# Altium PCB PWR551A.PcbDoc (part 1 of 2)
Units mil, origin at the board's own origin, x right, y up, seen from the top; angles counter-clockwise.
Board outline 7100 x 3800 mil, 2 copper layers (Top Layer, Bottom Layer), stack 62 mil thick; 141 components, 57 nets, 323 pads, 168 vias.
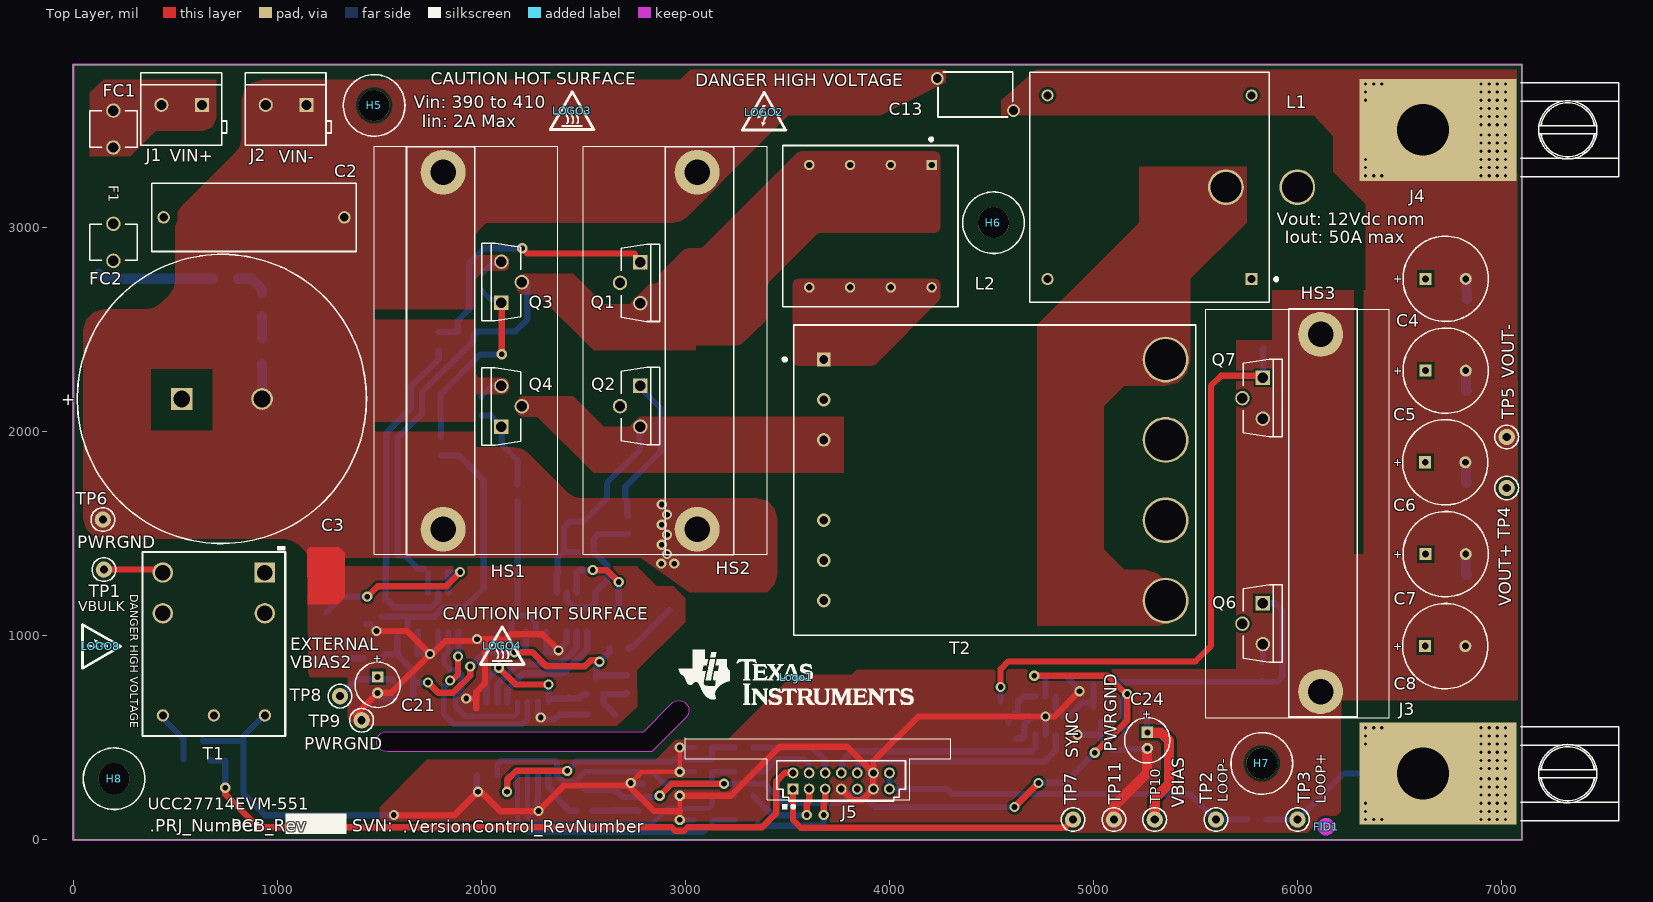
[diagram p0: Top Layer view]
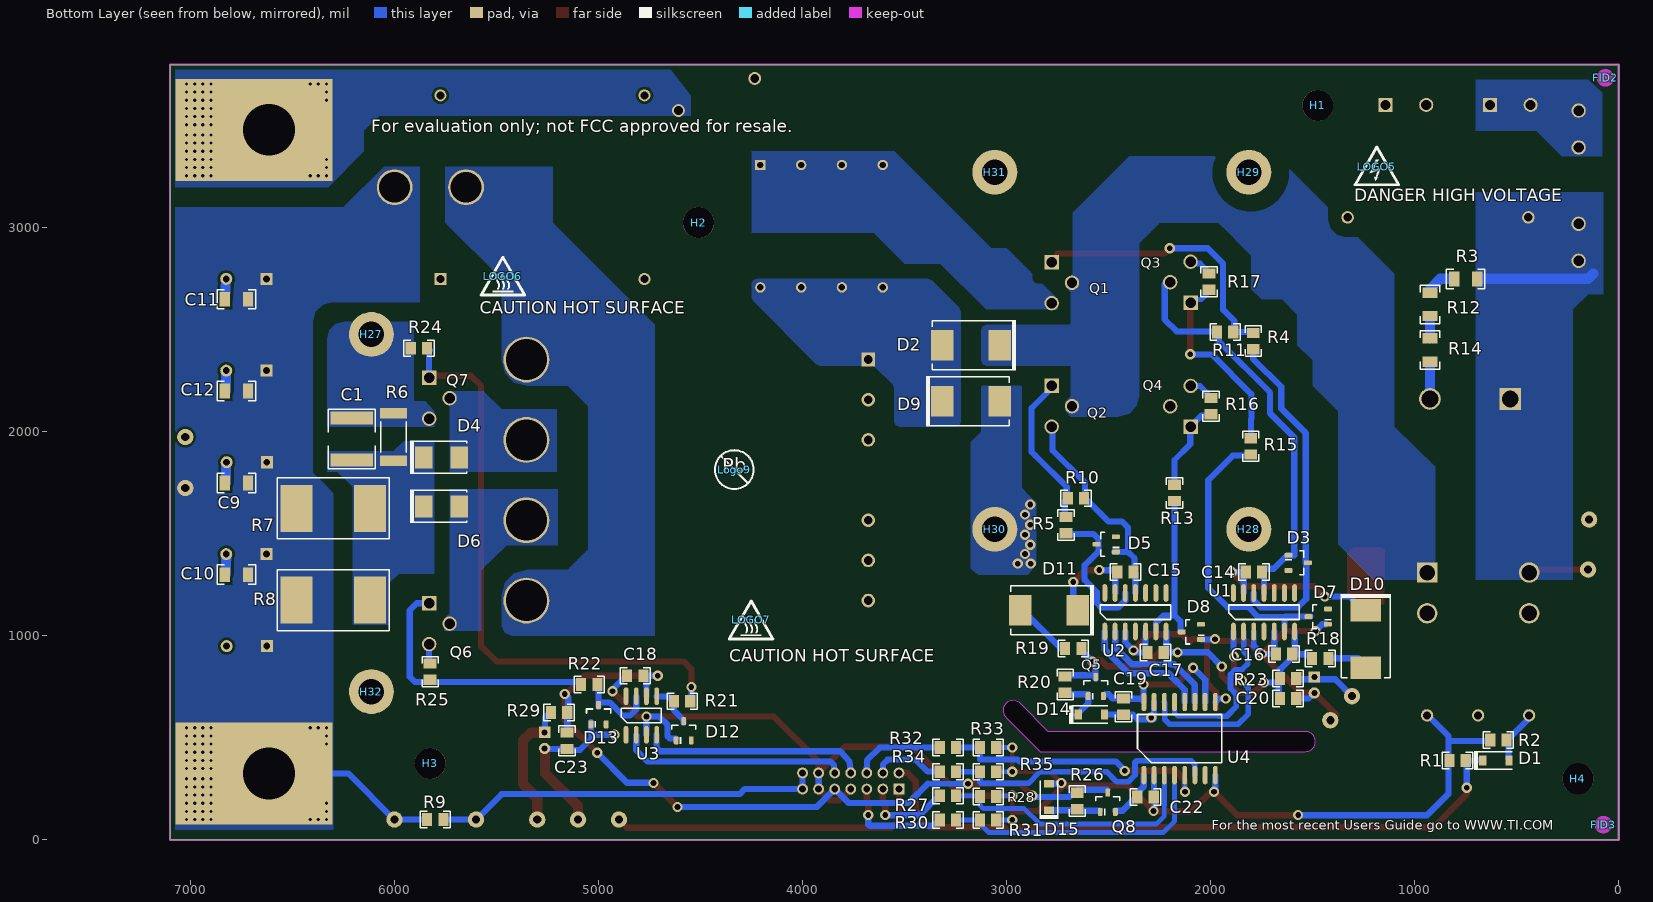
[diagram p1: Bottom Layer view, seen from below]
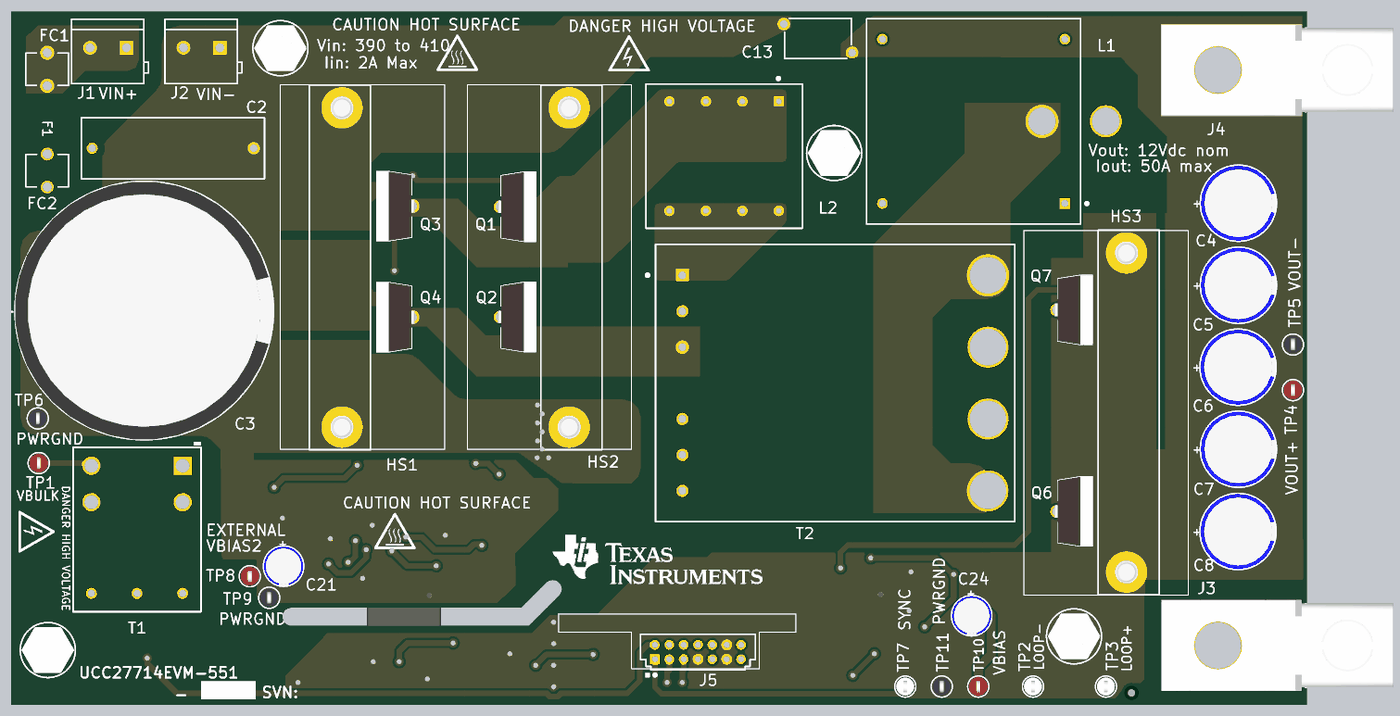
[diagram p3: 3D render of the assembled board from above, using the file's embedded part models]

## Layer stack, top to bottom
Top Layer: signal copper 1.4
Dielectric: core 59.2, FR-4, Dk 4.8
Bottom Layer: signal copper 1.4

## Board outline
0,0 0,3800 7100,3800 7100,0
cut-out: 1535.43,433.07 cw(c1535.43,482.28) 1535.43,531.5 2795.28,531.5 2933.07,669.29 cw(c2967.87,634.49) 3002.67,599.69 2836.04,433.07

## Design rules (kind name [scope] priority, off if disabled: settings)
AcuteAngle [All] p1: minimum=4.50000000000000E+0001 checktracksonly=TRUE
AssemblyTestPointUsage [All] p1: valid=2
Clearance Clearance-PRI-SEC [InNetClass('SEC') vs InNetClass('HV') OR InNetClass('SW') OR InNetClass('LV')] p1: gap=314.96
Clearance ClearanceHV [InNetClass('HV') vs InNetClass('All Nets')] p2: gap=39.37
Clearance ClearanceSW [InNetClass('SW') vs InNetClass('HV') OR InNetClass('LV')] p3: gap=39.37
Clearance Clearance_Poly [InPolygon] p4: gap=12
Clearance Clearance_BoardEdge_MountingHoles [OnCopper and InComponentClass('Mounting Holes') vs IsKeepOut] p5: gap=12
Clearance Clearance_BoardEdge_Poly [OnCopper and InPoly vs IsKeepOut] p6: gap=19.68
Clearance Clearance_BoardEdge [OnCopper and Not InComponentClass('Logo') and not InComponentClass('FiducialMark') and not InRegion(1000,500,4000,800) and Not IsKeepout vs IsKeepout] p7: gap=19.68
Clearance Clearance_ALL [All] p8: gap=12
ComponentClearance ComponentClearance_Logo [InComponentClass(Logo)] p1: gap=3.94 collisioncheckmode=3 verticalgap=27.56 showdistances=FALSE
ComponentClearance ComponentClearance_ScrewToNut [(HasFootprint('NY PMS 440 0025 PH')) vs (HasFootprint('Keystone_1902C'))] p2: gap=0 collisioncheckmode=3 verticalgap=0 showdistances=FALSE
ComponentClearance ComponentClearance_MountingHoles [InComponentClass('Mounting Holes')] p3: gap=19.68 collisioncheckmode=3 verticalgap=27.56 showdistances=FALSE
ComponentClearance ComponentClearance_SmallPassives [HasFootprint('0201*') or HasFootprint('0402*') or HasFootprint('0508') or HasFootprint('0603*') or HasFootprint('0612') or HasFootprint('0805*') or HasFootprint('0815*') or HasFootprint('0830*') or HasFootprint('1206*') or HasFootprint('1210*') or HasFootprint('1808*') or HasFootprint('1812*') or HasFootprint('1825*') or HasFootprint('2010*') or HasFootprint('2220*') or HasFootprint('2225*') or HasFootprint('2512*') or HasFootprint('2728*') or HasFootprint('3518*') vs HasFootprint('0201*') or HasFootprint('0402*') or HasFootprint('0508') or HasFootprint('0603*') or HasFootprint('0612') or HasFootprint('0805*') or HasFootprint('0815*') or HasFootprint('0830*') or HasFootprint('1206*') or HasFootprint('1210*') or HasFootprint('1808*') or HasFootprint('1812*') or HasFootprint('1825*') or HasFootprint('2010*') or HasFootprint('2220*') or HasFootprint('2225*') or HasFootprint('2512*') or HasFootprint('2728*') or HasFootprint('3518*')] p4: gap=7.87 collisioncheckmode=3 verticalgap=10 showdistances=FALSE
ComponentClearance ComponentClearance_THtoSMT [IsThruComponent vs IsSMTComponent] p5 off: gap=7.87 collisioncheckmode=3 verticalgap=27.56 showdistances=FALSE
ComponentClearance ComponentClearance_THtoTH [IsThruComponent vs IsThruComponent] p6 off: gap=7.87 collisioncheckmode=3 verticalgap=27.56 showdistances=FALSE
ComponentClearance [All] p7: gap=0 collisioncheckmode=3 verticalgap=0 showdistances=FALSE
DiffPairsRouting [All] p1: maxlimit=100 minlimit=10 mostfreqgap=10 maxuncoupledlength=1000
FabricationTestPointUsage TestPointUsage [All] p1: valid=2 allowmultiple=FALSE
FabricationTestpoint Testpoint [All] p1: side=3 testpointundercomponent=TRUE minsize=40 maxsize=100 preferedsize=60 minholesize=0 maxholesize=40 preferedholesize=32 testpointgrid=1 allowsidetop=TRUE allowsidebottom=TRUE usegrid=TRUE gridtolerance=0.01
FanoutControl Fanout_LCC [IsLCC] p1: bgadir=Out bgaviamode=Centered fanoutstyle=Auto fanoutdirection=Alternating viagrid=1 // Fanout_LCC (Default Rule)
FanoutControl Fanout_BGA [IsBGA] p2: bgadir=Out bgaviamode=Centered fanoutstyle=Auto fanoutdirection=Alternating viagrid=1 // Fanout_BGA (Default Rule)
FanoutControl Fanout_Default [All] p4: bgadir=Out bgaviamode=Centered fanoutstyle=Auto fanoutdirection=Alternating viagrid=1 // Fanout_Default (Default Rule)
FanoutControl Fanout_Small [(CompPinCount < 5)] p5: bgadir=Out bgaviamode=Centered fanoutstyle=Auto fanoutdirection=OutThenIn viagrid=1 // Fanout_Small (Default Rule)
Height "Height Bottom" [(OnLayer('Bottom Layer'))] p1: minheight=0 maxheight=1000 prefheight=500
Height Height_top [(OnLayer('Top Layer'))] p2: minheight=0 maxheight=1750 prefheight=1750
HoleSize [All] p1: absolutevalues=TRUE maxlimit=275.59 minlimit=8 maxpercent=80.000 minpercent=20.000
MinimumAnnularRing [All] p1: minimumring=8
MinimumSolderMaskSliver MinimumSolderMaskSliver_Logo [InComponentClass('Logo') vs InComponentClass('Logo')] p1: minsoldermaskwidth=0.7
MinimumSolderMaskSliver [All] p2: minsoldermaskwidth=4
PlaneConnect [All] p1: planeconnectstyle=Relief reliefexpansion=10 reliefentries=4 reliefconductorwidth=10 reliefairgap=10
PolygonConnect PolygonConnect_23 [All vs IsNamedPolygon('Top Layer, Top-PWRGND 4')] p1: connectstyle=Direct reliefconductorwidth=10 reliefentries=4 polygonreliefangle="90 Angle" airgapwidth=10
PolygonConnect PolygonConnect_22 [All vs IsNamedPolygon('Top Layer, Top-PWRGND 4')] p2: connectstyle=Direct reliefconductorwidth=10 reliefentries=4 polygonreliefangle="90 Angle" airgapwidth=10
PolygonConnect PolygonConnect_21 [All vs IsNamedPolygon('Top Layer, Top-PWRGND 2')] p3: connectstyle=Direct reliefconductorwidth=10 reliefentries=4 polygonreliefangle="90 Angle" airgapwidth=10
PolygonConnect PolygonConnect_20 [All vs IsNamedPolygon('Top Layer, Top-PWRGND 3')] p4: connectstyle=Direct reliefconductorwidth=10 reliefentries=4 polygonreliefangle="90 Angle" airgapwidth=10
PolygonConnect PolygonConnect_19 [All vs IsNamedPolygon('Top Layer, Top-PWRGND 4')] p5: connectstyle=Direct reliefconductorwidth=10 reliefentries=4 polygonreliefangle="90 Angle" airgapwidth=10
PolygonConnect PolygonConnect_18 [All vs IsNamedPolygon('Top Layer, Top-GND')] p6: connectstyle=Direct reliefconductorwidth=10 reliefentries=4 polygonreliefangle="90 Angle" airgapwidth=10
PolygonConnect PolygonConnect_17 [All vs IsNamedPolygon('Top Layer, Top-GND 1')] p7: connectstyle=Direct reliefconductorwidth=10 reliefentries=4 polygonreliefangle="90 Angle" airgapwidth=10
PolygonConnect PolygonConnect_16 [All vs IsNamedPolygon('Top Layer, Top-GND 2')] p8: connectstyle=Direct reliefconductorwidth=10 reliefentries=4 polygonreliefangle="90 Angle" airgapwidth=10
PolygonConnect PolygonConnect_15 [All vs IsNamedPolygon('Top Layer, Top-NET00002')] p9: connectstyle=Direct reliefconductorwidth=10 reliefentries=4 polygonreliefangle="90 Angle" airgapwidth=10
PolygonConnect PolygonConnect_14 [All vs IsNamedPolygon('Top Layer, Top-NET00003')] p10: connectstyle=Direct reliefconductorwidth=10 reliefentries=4 polygonreliefangle="90 Angle" airgapwidth=10
PolygonConnect PolygonConnect_13 [All vs IsNamedPolygon('Top Layer, Top-NET00003')] p11: connectstyle=Direct reliefconductorwidth=10 reliefentries=4 polygonreliefangle="90 Angle" airgapwidth=10
PolygonConnect PolygonConnect_12 [All vs IsNamedPolygon('Top Layer, Top-NET00007')] p12: connectstyle=Direct reliefconductorwidth=10 reliefentries=4 polygonreliefangle="90 Angle" airgapwidth=10
PolygonConnect PolygonConnect_11 [All vs IsNamedPolygon('Top Layer, Top-NET00016')] p13: connectstyle=Direct reliefconductorwidth=10 reliefentries=4 polygonreliefangle="90 Angle" airgapwidth=10
PolygonConnect PolygonConnect_10 [All vs IsNamedPolygon('Top Layer, Top-NET00025')] p14: connectstyle=Direct reliefconductorwidth=10 reliefentries=4 polygonreliefangle="90 Angle" airgapwidth=10
PolygonConnect PolygonConnect_9 [All vs IsNamedPolygon('Top Layer, Top-NET00025 1')] p15: connectstyle=Direct reliefconductorwidth=10 reliefentries=4 polygonreliefangle="90 Angle" airgapwidth=10
PolygonConnect PolygonConnect_8 [All vs IsNamedPolygon('Top Layer, Top-No Net')] p16: connectstyle=Direct reliefconductorwidth=10 reliefentries=4 polygonreliefangle="90 Angle" airgapwidth=10
PolygonConnect PolygonConnect_7 [All vs IsNamedPolygon('Top Layer, Top-PWRGND')] p17: connectstyle=Direct reliefconductorwidth=10 reliefentries=4 polygonreliefangle="90 Angle" airgapwidth=10
PolygonConnect PolygonConnect_6 [All vs IsNamedPolygon('Top Layer, Top-PWRGND 1')] p18: connectstyle=Direct reliefconductorwidth=10 reliefentries=4 polygonreliefangle="90 Angle" airgapwidth=10
PolygonConnect PolygonConnect_5 [All vs IsNamedPolygon('Top Layer, Top-PWRGND 2')] p19: connectstyle=Direct reliefconductorwidth=10 reliefentries=4 polygonreliefangle="90 Angle" airgapwidth=10
PolygonConnect PolygonConnect_4 [All vs IsNamedPolygon('Top Layer, Top-PWRGND 3')] p20: connectstyle=Direct reliefconductorwidth=10 reliefentries=4 polygonreliefangle="90 Angle" airgapwidth=10
PolygonConnect PolygonConnect_3 [All vs IsNamedPolygon('Top Layer, Top-PWRGND 4')] p21: connectstyle=Direct reliefconductorwidth=10 reliefentries=4 polygonreliefangle="90 Angle" airgapwidth=10
PolygonConnect PolygonConnect_2 [All vs IsNamedPolygon('Top Layer, Top-PWRGND 3') Or  IsNamedPolygon('Top Layer, Top-PWRGND 4')] p22: connectstyle=Direct reliefconductorwidth=10 reliefentries=4 polygonreliefangle="90 Angle" airgapwidth=10
PolygonConnect PolygonConnect_1 [All vs IsNamedPolygon('Top Layer, Top-PWRGND 2') Or  IsNamedPolygon('Bottom Layer, Bottom-GND') Or  IsNamedPolygon('Bottom Layer, Bottom-NET00038') Or  IsNamedPolygon('Bottom Layer, Bottom-NET00006') Or  IsNamedPolygon('Bottom Layer, Bottom-NET00003') Or  IsNamedPolygon('Bottom Layer, Bottom-NET00004 2') Or  IsNamedPolygon('Bottom Layer, Bottom-NET00020') Or  IsNamedPolygon('Bottom Layer, Bottom-GND 2') Or  IsNamedPolygon('Bottom Layer, Bottom-NET00004') Or  IsNamedPolygon('Bottom Layer, Bottom-PWRGND') Or  IsNamedPolygon('Bottom Layer, Bottom-NET00002 1') Or  IsNamedPolygon('Bottom Layer, Bottom-NET00013') Or  IsNamedPolygon('Bottom Layer, Bottom-NET00012') Or  IsNamedPolygon('Bottom Layer, Bottom-NET00004 3') Or  IsNamedPolygon('Bottom Layer, Bottom-NET00004 1') Or  IsNamedPolygon('Bottom Layer, Bottom-NET00016') Or  IsNamedPolygon('Bottom Layer, Bottom-GND 1') Or  IsNamedPolygon('Bottom Layer, Bottom-NET00025') Or  IsNamedPolygon('Bottom Layer, Bottom-NET00002') Or  IsNamedPolygon('Top Layer, Top-No Net') Or  IsNamedPolygon('Top Layer, Top-NET00016') Or  IsNamedPolygon('Top Layer, Top-NET00025 1') Or  IsNamedPolygon('Top Layer, Top-GND 2') Or  IsNamedPolygon('Top Layer, Top-PWRGND 3') Or  IsNamedPolygon('Top Layer, Top-PWRGND 4') Or  IsNamedPolygon('Top Layer, Top-NET00002') Or  IsNamedPolygon('Top Layer, Top-NET00007') Or  IsNamedPolygon('Top Layer, Top-GND 1') Or  IsNamedPolygon('Top Layer, Top-PWRGND 1') Or  IsNamedPolygon('Top Layer, Top-GND') Or  IsNamedPolygon('Top Layer, Top-NET00025') Or  IsNamedPolygon('Top Layer, Top-NET00003') Or  IsNamedPolygon('Top Layer, Top-PWRGND')] p23: connectstyle=Direct reliefconductorwidth=10 reliefentries=4 polygonreliefangle="90 Angle" airgapwidth=10
PolygonConnect [All] p24: connectstyle=Relief reliefconductorwidth=10 reliefentries=4 polygonreliefangle="90 Angle" airgapwidth=10
RoutingVias [All] p1: holewidth=16 width=34 viastyle="Through Hole" minholewidth=8 minwidth=26 maxholewidth=40 maxwidth=65
SMDToCorner [All] p1: distance=30000
SilkToSilkClearance [All] p1 off: silktosilkclearance=4.5
SilkscreenOverComponentPads [All] p1: minsilkscreentomaskgap=5
SolderMaskExpansion [All] p1: expansion=3
Width [All] p1: maxlimit=100 minlimit=19.68 preferedwidth=31.5 checkconnectedcopper=TRUE
13 further rules are at their usual default settings.

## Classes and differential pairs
component class Screw: H27 H28 H29 H30 H31 H32
net class SW: NetC14_1 NetC15_1
net class HV: NetC2_2 NetD2_1 NetF1_1 NetF1_2 NetFC1_1 NetR3_1 NetR12_1
net class SEC: CS GND NetC1_2 NetC4_1 NetC22_2 NetC24_1 NetD1_2 NetD4_2 NetD6_2 NetD12_3 NetD13_3 NetD15_1 NetL1_13 NetQ6_1 NetQ7_1 NetR27_2 NetR30_2 NetR32_2 NetR34_2 NetU3_1 NetU3_8 NetU4_7 OUTA OUTB OUTC OUTD OUTE OUTF SYNC VBIAS VOUT
component class PWR551A_Sht01: C1 C2 C3 C4 C5 C6 C7 C8 C9 C10 C11 C12 C13 C14 C15 C16 C17 C18 C19 C20 C21 C22 C23 C24 D1 D2 D3 D4 D5 D6 D7 D8 D9 D10 D11 D12 D13 D14 D15 F1 FC1 FC2 HS1 HS2 HS3 J1 J2 J3 J4 J5 L1 L2 Q1 Q2 Q3 Q4 Q5 Q6 Q7 Q8 R1 R2 R3 R4 R5 R6 R7 R8 R9 R10 R11 R12 R13 R14 R15 R16 R17 R18 R19 R20 R21 R22 R23 R24 R25 R26 R27 R28 R29 R30 R31 R32 R33 R34 R35 T1 T2 TP1 TP2 TP3 TP4 TP5 TP6 TP7 TP8 TP9 TP10 TP11 U1 U2 U3 U4
component class PWR551A_Hardware: !PCB FID1 FID2 FID3 H1 H2 H3 H4 H5 H6 H7 H8 H27 H28 H29 H30 H31 H32 Logo1 LOGO2 LOGO3 LOGO4 LOGO5 LOGO6 LOGO7 LOGO8 Logo9 ZZ1 ZZ2 ZZ3 ZZ4
component class Logo: Logo1
component class FiducialMark: FID1 FID2 FID3
component class AssemblyNote: ZZ1 ZZ2 ZZ3 ZZ4

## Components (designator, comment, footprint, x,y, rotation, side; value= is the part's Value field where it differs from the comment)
C1 "C2220C224J1GACTU" 2220 6210,1965 r270 bottom
C2 "ECQ-U2A474ML" CAPRR2250W80L2550T850H1750 885.83,3051.18 r180 top
C3 "EET-HC2W331EA" TS-HC_3500x3500 728.35,2161.42 r0 top
C4 "EKY-160ELL152MJ30S" KY_1000x3000 6726,2750 r0 top
C5 "EKY-160ELL152MJ30S" KY_1000x3000 6726,2300 r0 top
C6 "EKY-160ELL152MJ30S" KY_1000x3000 6724,1851 r0 top
C7 "EKY-160ELL152MJ30S" KY_1000x3000 6726,1401 r0 top
C8 "EKY-160ELL152MJ30S" KY_1000x3000 6724,950 r0 top
C9 "C3216X7R1E105K085AA" 1206 6775,1750 r180 bottom
C10 "C3216X7R1E105K085AA" 1206 6775,1300 r180 bottom
C11 "C3216X7R1E105K085AA" 1206 6775,2650 r180 bottom
C12 "C3216X7R1E105K085AA" 1206 6775,2200 r180 bottom
C13 "440LD10-R" 440L_930x1250 4421.26,3653.54 r180 top
C14 "C2012X7R1H104K" 0805_HV 1787.8,1312.99 r0 bottom
C15 "C2012X7R1H104K" 0805_HV 2417.72,1312.99 r0 bottom
C16 "C2012X7R1E105K" 0805_HV 1640.16,910.87 r180 bottom
C17 "C2012X7R1E105K" 0805_HV 2270.08,919.29 r180 bottom
C18 "C2012X7R1E105K" 0805_HV 4820,805 r180 bottom
C19 "C2012X7R1E105K" 0805_HV 2427.56,653.54 r90 bottom
C20 "C2012X7R1E105K" 0805_HV 1620.47,692.91 r0 bottom
C21 "ECA-1VM220" M_500x1100 1492.13,759.84 r270 top
C22 "C2012X7R1E105K" 0805_HV 2319.29,210.63 r0 bottom
C23 "C2012X7R1E105K" 0805_HV 5153.94,486.22 r90 bottom
C24 "ECA-1VM220" M_500x1100 5263.78,488.19 r270 top
D1 "1N4148W-7-F" SOD-123 602.36,389.76 r180 bottom
D2 "MURS360T3G" SMC 3175,2425 r0 bottom
D3 "BAT54-7-F" SOT-23 1570.87,1358.27 r180 bottom
D4 "ES3BB-13-F" SMB 5770,1875 r180 bottom
D5 "BAT54-7-F" SOT-23 2511.81,1448.82 r0 bottom
D6 "ES3BB-13-F" SMB 5770,1635 r180 bottom
D7 "BAT54-7-F" SOT-23 1472.44,1094.49 r0 bottom
D8 "BAT54-7-F" SOT-23 2094.49,1019.68 r0 bottom
D9 "MURS360T3G" SMC 3175,2150 r180 bottom
D10 "MURS360T3G" SMC 1240.16,984.25 r270 bottom
D11 "MURS360T3G" SMC 2791.73,1125.98 r0 bottom
D12 "BAT54-7-F" SOT-23 4582.68,535.43 r90 bottom
D13 "BAT54-7-F" SOT-23 5000,614.17 r90 bottom
D14 "MMSZ5232B-7-F" SOD-123 2585.04,614.17 r180 bottom
D15 "MMSZ5232B-7-F" SOD-123 2791.73,210.63 r90 bottom
FC1 "01000056Z" Littelfuse_0100-0020_54_56 196.85,3484.25 r90 top
FC2 "01000056Z" Littelfuse_0100-0020_54_56 196.85,2929.13 r270 top
FID1 "Fiducial" Fiducial10-20 6140,65 r0 top
FID2 "Fiducial" Fiducial10-20 65,3735 r180 bottom (schematic designator FID3)
FID3 "Fiducial" Fiducial10-20 75,75 r180 bottom (schematic designator FID2)
H1 "1903C" KEYSTONE_1903C 1474.9,3600.1 r180 bottom locked (schematic designator H4)
H2 "1903C" KEYSTONE_1903C 4509.9,3025.1 r180 bottom locked (schematic designator H1)
H3 "1903C" KEYSTONE_1903C 5824.9,375.1 r180 bottom locked (schematic designator H2)
H4 "1903C" KEYSTONE_1903C 200,300 r180 bottom locked (schematic designator H3)
H5 "4826" KEYSTONE_4826 1474.9,3600.1 r0 top locked (schematic designator H8)
H6 "4826" KEYSTONE_4826 4509.9,3025.1 r0 top locked (schematic designator H5)
H7 "4826" KEYSTONE_4826 5824.9,375.1 r0 top locked (schematic designator H6)
H8 "4826" KEYSTONE_4826 200,300 r0 top locked (schematic designator H7)
H27 "MPMS 003 0005 PH" BuildingFastener_MPMS_003_0005_PH 6112.81,2477.36 r180 bottom
H28 "MPMS 003 0005 PH" BuildingFastener_MPMS_003_0005_PH 1812.39,1522.64 r180 bottom
H29 "MPMS 003 0005 PH" BuildingFastener_MPMS_003_0005_PH 1812.39,3272.64 r180 bottom
H30 "MPMS 003 0005 PH" BuildingFastener_MPMS_003_0005_PH 3057.69,1522.64 r180 bottom
H31 "MPMS 003 0005 PH" BuildingFastener_MPMS_003_0005_PH 3057.69,3272.64 r180 bottom
H32 "MPMS 003 0005 PH" BuildingFastener_MPMS_003_0005_PH 6112.81,727.36 r180 bottom
HS1 "782653B02000G" HEATSINK_782653B02000G 1913.39,2397.64 r270 top
HS2 "782653B02000G" HEATSINK_782653B02000G 2956.69,2397.64 r90 top
HS3 "782653B02000G" HEATSINK_782653B02000G 6011.81,1602.36 r90 top
J1 "VIN+" CONN_ED120-2DS 531.5,3602.36 r90 top
J2 "VIN-" CONN_ED120-2DS 1043.31,3602.36 r90 top
J3 "CXS70-14-C" Panduit_CXS70-14-C 6614.17,325 r180 top locked
J4 "CXS70-14-C" Panduit_CXS70-14-C 6614.17,3480.32 r180 top
J5 "DF11-14DS-2DSA(05)" Hirose_DF11-14DS-2DSA[05] 3763.9,289.05 r90 top
L1 "75PR8108" 75P 5387,3199 r180 top
L2 "60PR964" 60P 3907,3008 r270 top
Logo1 "Texas Instruments" TI_Stacked_Overlay_Medium 3543.31,797.24 r0 top
LOGO2 "DANGER HIGH VOLTAGE" IEC_HighVoltage_Small 3385.83,3566.93 r0 top
LOGO3 "CAUTION HOT SURFACE" IEC_HotSurface_Small 2444.88,3574.8 r0 top
LOGO4 "CAUTION HOT SURFACE" IEC_HotSurface_Small 2102.36,952.76 r0 top
LOGO5 "DANGER HIGH VOLTAGE" IEC_HighVoltage_Small 1185.04,3299.21 r180 bottom
LOGO6 "CAUTION HOT SURFACE" IEC_HotSurface_Small 5468.5,2763.78 r180 bottom
LOGO7 "CAUTION HOT SURFACE" IEC_HotSurface_Small 4251.97,1078.74 r180 bottom
LOGO8 "DANGER HIGH VOLTAGE" IEC_HighVoltage_Small 133.86,948.82 r270 top
Logo9 "Pb-Free Symbol" Pb-Free_Overlay_Medium 4334.65,1814.96 r180 bottom
Q1 "SPP20N60C3" TO-220AB_100mil 2779.53,2830.71 r270 top
Q2 "SPP20N60C3" TO-220AB_100mil 2779.53,2225.98 r270 top
Q3 "SPP20N60C3" TO-220AB_100mil 2098.43,2633.86 r90 top
Q4 "SPP20N60C3" TO-220AB_100mil 2098.43,2025 r90 top
Q5 "MMBT2222A" SOT-23 2562.99,751.97 r90 bottom
Q6 "CSD19506KCS" TO-220AB_100mil 5830,1160 r270 top
Q7 "CSD19506KCS" TO-220AB_100mil 5830,2265 r270 top
Q8 "MMBT2222A" SOT-23 2503.94,185.04 r90 bottom
R1 "CRCW080548R7FKEA" 0805_HV 790,390 r0 bottom
R2 "ERJ-6ENF4871V" 0805_HV 590,490 r0 bottom
R3 "CRCW12061M00JNEA" 1206 750,2750 r180 bottom
R4 "CRCW08053R01FKEA" 0805_HV 1791.34,2444.88 r90 bottom
R5 "CRCW08053R01FKEA" 0805_HV 2708.66,1543.31 r90 bottom
R6 "CRCW2512100KFKEG" 2512 6005,1975 r90 bottom
R7 "WSC45271K000FEA" 4527_450 6300,1625 r180 bottom
R8 "WSC45271K000FEA" 4527_450 6300,1175 r180 bottom
R9 "ERJ-6ENF49R9V" 0805_HV 5800,100 r0 bottom
R10 "ERJ-6ENF1002V" 0805_HV 2660,1675 r0 bottom
R11 "ERJ-6ENF1002V" 0805_HV 1929.13,2490.16 r0 bottom
R12 "CRCW12061M00JNEA" 1206 925,2625 r90 bottom
R13 "CRCW08053R01FKEA" 0805_HV 2177.17,1700.79 r90 bottom
R14 "CRCW12061M00JNEA" 1206 925,2401.57 r90 bottom
R15 "CRCW08053R01FKEA" 0805_HV 1803.15,1929.13 r90 bottom
R16 "ERJ-6ENF1002V" 0805_HV 1998.03,2125.98 r90 bottom
R17 "ERJ-6ENF1002V" 0805_HV 2007.87,2736.22 r90 bottom
R18 "ERJ-6RQF2R2V" 0805_HV 1462.99,889.76 r180 bottom
R19 "ERJ-6RQF2R2V" 0805_HV 2673.62,938.98 r0 bottom
R20 "ERJ-6ENF7151V" 0805_HV 2712.99,761.81 r270 bottom
R21 "CRCW08056R19FKEA" 0805_HV 4590,680 r180 bottom
R22 "CRCW08056R19FKEA" 0805_HV 5045.67,761.81 r0 bottom
R23 "CRCW08055R11FKEA" 0805_HV 1620.47,791.34 r180 bottom
R24 "ERJ-6ENF1002V" 0805_HV 5880,2410 r0 bottom
R25 "ERJ-6ENF1002V" 0805_HV 5825,825 r90 bottom
R26 "ERJ-6ENF7151V" 0805_HV 2653.94,190.94 r270 bottom
R27 "ERJ-6ENF7151V" 0805_HV 3287.4,216.54 r180 bottom
R28 "ERJ-6ENF5111V" 0805_HV 3090.55,212.6 r0 bottom
R29 "CRCW08055R11FKEA" 0805_HV 5193.31,624.02 r0 bottom
R30 "ERJ-6ENF7151V" 0805_HV 3287.4,98.43 r180 bottom
R31 "ERJ-6ENF5111V" 0805_HV 3090.55,98.43 r0 bottom
R32 "ERJ-6ENF7151V" 0805_HV 3287.4,452.76 r180 bottom
R33 "ERJ-6ENF5111V" 0805_HV 3090.55,452.76 r0 bottom
R34 "ERJ-6ENF7151V" 0805_HV 3287.4,334.65 r180 bottom
R35 "ERJ-6ENF5111V" 0805_HV 3090.55,334.65 r0 bottom
T1 "PE-63587" Pulse_PE6358X 688.98,960.63 r270 top
T2 "75PR8107" VITEC_75PR8107 4515.75,1763.78 r0 top
TP1 "VBULK" Keystone5000 150,1325 r0 top
TP2 "LOOP-" Keystone5002 5600,100 r0 top
TP3 "LOOP+" Keystone5002 6000,100 r0 top
TP4 "VOUT+" Keystone5000 7025,1725 r0 top
TP5 "VOUT-" Keystone5001 7025,1975 r0 top
TP6 "PWRGND" Keystone5001 145,1570 r0 top
TP7 "SYNC" Keystone5002 4900,100 r0 top
TP8 "VBIAS2" Keystone5000 1307.09,704.72 r0 top
TP9 "PWRGND" Keystone5001 1413.39,586.61 r0 top
TP10 "VBIAS" Keystone5000 5300,100 r0 top
TP11 "PWRGND" Keystone5001 5100,100 r0 top
U1 "UCC27714D" D0014A_N 1738.58,1116.14 r90 bottom
U2 "UCC27714D" D0014A_N 2368.5,1116.14 r90 bottom
U3 "UCC27524AD" D0008A_N 4790,610 r90 bottom
U4 "ISO7240MDW" DW0016A_N 2152,497 r90 bottom
ZZ1 "See assembly document for heatsink assembly instructions." AssemblyNote 20.28,6930.68 r0 top
ZZ2 "These assemblies are ESD sensitive, ESD precautions shall be observed." AssemblyNote 20.28,6821.79 r0 top
ZZ3 "These assemblies must be clean and free from flux and all contaminants. Use of no clean flux is not acceptable." AssemblyNote 20.28,6733.23 r0 top
ZZ4 "These assemblies must comply with workmanship standards IPC-A-610 Class 2., unless otherwise specified." AssemblyNote 20.28,6644.68 r0 top

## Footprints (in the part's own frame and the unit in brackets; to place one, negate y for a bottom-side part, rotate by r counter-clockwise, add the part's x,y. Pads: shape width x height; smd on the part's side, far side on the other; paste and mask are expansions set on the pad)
60P [mm] "VITEC"
  rect 1.3x1.3 hole 0.8: 1(-7.62,7.62)
  round 1.3 hole 0.8: 2(-7.62,2.54) 3(-7.62,-2.54) 4(-7.62,-7.62) 5(7.62,-7.62) 6(7.62,-2.54) 7(7.62,2.54) 8(7.62,7.62)
  silkscreen extent -10.94,-10.9 10.05,10.9, body extent -10.05,-10.9 10.05,10.9, height 16.52
75P [mm] "VITEC"
  rect 1.5x1.5 hole 1: 1(-9.85,11.43)
  round 1.5 hole 1: 6(-9.85,-11.43) 7(15.55,-11.43) 12(15.55,11.43)
  round 4.45 hole 3.85: 13(-6.66,0) 14(-15.55,0)
  silkscreen extent -13.04,-14.3 17.75,14.3, body extent -17.31,-14.3 17.75,14.3, height 25.31
440L_930x1250 [mm] "Vishay"
  round 1.6 hole 1.092: 1(-4.75,2) 2(4.75,-2)
  silkscreen extent -4.65,-2.8 4.65,2.8, body extent -5.25,-2.8 5.25,2.8, height 12.46
0805_HV [mil] "0805 with 30mil clearance between pads"
  rect 50x63 smd: 1(-40,0) 2(40,0)
  silkscreen extent -74,-40 74,40, body extent -43,-29 43,29, height 43
1206 [mm] "1206 from SM-752 data"
  rect 1.3x1.85 smd: 1(-1.45,0) 2(1.45,0)
  silkscreen extent -2.4,-1.21 2.4,1.21, body extent -1.7,-0.9 1.7,0.9, height 1.35
2220 [mm] "Chip Capacitor, Body 5.7x5.0mm, IPC Medium Density"
  rect 1.6x5.3 smd: 1(-2.6,0) 2(2.6,0)
  silkscreen extent -3.69,-2.94 3.69,2.94, body extent -2.95,-2.62 2.95,2.62, height 1.35
2512 [mm] "Chip Resistor, Body 6.3x3.2mm, IPC Medium Density"
  rect 1.3x3.4 smd: 1(-2.95,0) 2(2.95,0)
  silkscreen extent -1.9,-1.6 1.9,1.6, body extent -3.22,-1.67 3.22,1.67, height 0.71
4527_450 [mil] "Vishay recommended land pattern"
  rect 155x230 smd: 1(-180,0) 2(180,0)
  silkscreen extent -275,-150 275,150, body extent -227,-138 228,137, height 177
AssemblyNote [mil] "Assembly Note"
BuildingFastener_MPMS_003_0005_PH [mil] "MACHINE SCREW PAN PHILLIPS M3"
  round 1 on Mech4: 0(0,0)
  body extent -118,-118 118,118, height 93
CAPRR2250W80L2550T850H1750 [mm] "PANASONIC"
  round 1.55 hole 1.05: 1(-11.25,0) 2(11.25,0)
  silkscreen extent -12.75,-4.25 12.75,4.25, body extent -12.75,-4.25 12.75,4.25, height 17.5
CONN_ED120-2DS [mm] "ONSHORE"
  rect 1.75x1.75 hole 1.25: 1(0,-2.54)
  round 1.75 hole 1.25: 2(0,2.54)
  silkscreen extent -5,-5.6 4,5.12, body extent -5,-5.6 4.15,5.12, height 13.1
D0008A_N [mm] "SOIC, 8-Leads, Body 4.9x3.9mm, Pitch 1.27mm, IPC Medium Density"
  oval 2.2x0.6 smd: 1(-2.4,1.905) 2(-2.4,0.635) 3(-2.4,-0.635) 4(-2.4,-1.905) 5(2.4,-1.905) 6(2.4,-0.635) 7(2.4,0.635) 8(2.4,1.905)
  silkscreen extent -0.9,-2.5 0.9,2.5, body extent -3,-2.45 3,2.45, height 1.63
D0014A_N [mm] "SOIC, 14-Leads, Body 8.7x3.9mm, Pitch 1.27mm, IPC Medium Density"
  oval 2.2x0.6 smd: 1(-2.4,3.81) 2(-2.4,2.54) 3(-2.4,1.27) 4(-2.4,0) 5(-2.4,-1.27) 6(-2.4,-2.54) 7(-2.4,-3.81) 8(2.4,-3.81) 9(2.4,-2.54) 10(2.4,-1.27) 11(2.4,0) 12(2.4,1.27) 13(2.4,2.54) 14(2.4,3.81)
  silkscreen extent -0.9,-4.4 0.9,4.4, body extent -3.02,-4.32 3.02,4.32, height 1.59
DW0016A_N [mm] "SOIC, 16-Leads, Body 10.3x7.5mm, Pitch 1.27mm, IPC Medium Density"
  oval 2.3x0.6 smd: 1(-4.55,4.445) 2(-4.55,3.175) 3(-4.55,1.905) 4(-4.55,0.635) 5(-4.55,-0.635) 6(-4.55,-1.905) 7(-4.55,-3.175) 8(-4.55,-4.445) 9(4.55,-4.445) 10(4.55,-3.175) 11(4.55,-1.905) 12(4.55,-0.635) 13(4.55,0.635) 14(4.55,1.905) 15(4.55,3.175) 16(4.55,4.445)
  silkscreen extent -3,-5.25 3,5.25, body extent -5.14,-5.13 5.14,5.13, height 2.5
Fiducial10-20 [mm]
  round 1 smd mask+0.5: 1(0,0)
  Top Layer keep-out circle w1.178: c0,0 r0.5
HEATSINK_782653B02000G [mil] "Aavid"
  round 220 hole 125: 1(-875,-101) 2(875,-101)
  silkscreen extent -1000,-280 1000,55, body extent -1004,-430 1000,430, height 1122
Hirose_DF11-14DS-2DSA[05] [mm] "Hirose"
  rect 1.35x1.35 hole 0.85: 1(-1,6)
  round 1.35 hole 0.85: 2(1,6) 3(-1,4) 4(1,4) 5(-1,2) 6(1,2) 7(-1,0) 8(1,0) 9(-1,-2) 10(1,-2) 11(-1,-4) 12(1,-4) 13(-1,-6) 14(1,-6)
  silkscreen extent -3.33,-7.99 2.5,8.01, body extent -2.5,-7.99 2.5,8.01, height 6.51
IEC_HighVoltage_Small [mil]
  silkscreen extent -107,-88 107,97
IEC_HotSurface_Small [mil]
  silkscreen extent -107,-93 107,92
Keystone5000 [mil] "For Keystone 500x miniature loop terminals"
  round 80 hole 40: 1(0,0)
  silkscreen extent -58,-58 58,58, body extent -49,-49 49,49, height 182
Keystone5001 [mil] "For Keystone 500x miniature loop terminals"
  round 80 hole 40: 1(0,0)
  silkscreen extent -58,-58 58,58, body extent -49,-49 49,49, height 182
Keystone5002 [mil] "For Keystone 500x miniature loop terminals"
  round 80 hole 40: 1(0,0)
  silkscreen extent -58,-58 58,58, body extent -49,-49 49,49, height 182
KEYSTONE_1903C [mil] "HEX NYLON STANDOFF 6-32, F-F 0.5\""
  round 1 on Mech4: 0(0,0)
  body extent -144,-125 144,125, height 501
KEYSTONE_4826 [mil] "HEX STANDOFF 6-32 NYLON 1750 mil"
  round 1 on Mech3: 0(0,0)
  round 152 hole 152 unplated: MH(0,0)
  silkscreen extent -151,-151 151,151, body extent -144,-125 144,125, height 1751
KY_1000x3000 [mm] "NIPPON CHEMICON"
  rect 1.5x1.5 hole 0.85: 1(-2.5,0)
  round 1.5 hole 0.85: 2(2.5,0)
  silkscreen extent -5.3,-5.31 5.31,5.31, body extent -5.21,-5.24 5.24,5.24, height 31.51
Littelfuse_0100-0020_54_56 [mm] "Littelfuse"
  round 1.8 hole 1.3: 1(-2.3,0) 2(2.3,0)
  silkscreen extent -2.25,-2.97 2.25,2.97, body extent -2.55,-2.97 2.55,2.97, height 10.6
M_500x1100 [mm] "PANASONIC"
  rect 1.4x1.4 hole 0.75: 1(-1,0)
  round 1.4 hole 0.75: 2(1,0)
  silkscreen extent -2.82,-2.81 2.82,2.82, body extent -2.73,-2.75 2.75,2.75, height 12.01
Panduit_CXS70-14-C [mil] "Panduit"
  rect 770x500 hole 254 copper offset -74.8,0 paste-250: 1(0,0)
  silkscreen extent -960,-230 -480,230, body extent -960,-250 310,250, height 684
Pb-Free_Overlay_Medium [mil]
  silkscreen extent -95,-95 95,95
Pulse_PE6358X [mil] "Pulse"
  rect 100x100 hole 76 paste+0: 1(-350,250)
  round 100 hole 76 paste+0: 2(-350,-250) 6(-150,250) 7(-150,-250)
  round 60 hole 40 paste+0: 3(350,250) 4(350,0) 5(350,-250)
  silkscreen extent -480,-350 450,350, body extent -450,-350 450,350, height 700
SMB [mil] "Molded Diode, 2-Leads, Body 5.4x3.6mm, IPC Medium Density, based on OnSemi component dimensions"
  rect 85x107.99 smd: 1(-87.01,0) 2(87.01,0)
  silkscreen extent -155,-82 125,82, body extent -106,-71 106,71, height 91
SMC [mil] "Molded Diode, 2-Leads, Body 6.9x5.8mm, IPC Medium Density, based on OnSemi component dimensions and land patterns"
  rect 110x150 smd: 1(-140.49,0) 2(140.49,0)
  silkscreen extent -221,-124 189,124, body extent -156,-116 156,116, height 91
SOD-123 [mm] "On Semi recommended land pattern"
  rect 0.915x1.22 smd: 1(-1.637,0) 2(1.637,0)
  silkscreen extent -2.74,-1.17 2.03,1.17, body extent -1.93,-0.9 1.93,0.9, height 1.35
SOT-23 [mm] "SOT23, 3-Leads, Body 2.9x1.3mm, Pitch 0.95mm, Lead Span 2.5mm, IPC Medium Density"
  rrect50% 1x0.6 smd: 1(-1.2,0.95) 2(-1.2,-0.95) 3(1.2,0)
  silkscreen extent -1.62,-1.5 0.7,1.5, body extent -1.16,-1.45 1.21,1.45, height 1
TI_Stacked_Overlay_Medium [mil]
  silkscreen extent -576,-136 576,134
TO-220AB_100mil [mm] "High Voltage staggered pins"
  rect 1.8x1.8 hole 1.3: 1(0,0)
  round 1.8 hole 1.3: 2(2.54,-2.54) 3(5.08,0)
  silkscreen extent -2.29,-2.41 7.36,2.43, body extent -2.28,-2.84 7.37,2.43, height 22.88
TS-HC_3500x3500 [mm] "Panasonic"
  rect 2.7x2.7 hole 2.1: 1(-5,0)
  round 2.7 hole 2.1: 2(5,0)
  silkscreen extent -18,-18 18,18, body extent -17.9,-17.97 17.9,17.97, height 37
VITEC_75PR8107 [mm] "VITEC"
  rect 1.7x1.7 hole 1.1: 1(-21.275,15)
  round 1.7 hole 1.1: 2(-21.275,10) 3(-21.275,5) 4(-21.275,-5) 5(-21.275,-10) 6(-21.275,-15)
  round 5.7 hole 5.1: 7(21.275,-15) 9(21.275,-5) 10(21.275,5) 12(21.275,15)
  silkscreen extent -26.27,-19.31 25.01,19.31, body extent -25.01,-19.31 25.01,19.31, height 37.56

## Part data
C1: "CAP, CERM, 0.22uF, 100V, +/-5%, C0G/NP0, 2220"
C2: "CAP, Film, 0.47uF, 275V, +/-20%, TH"
C3: "CAP, AL, 330uF, 450V, +/-20%, 0.553 ohm, TH"
C4 C5 C6 C7 C8: "CAP, AL, 1500uF, 16V, +/-20%, 0.031 ohm, TH"
C9 C10 C11 C12: library part C3216X7R1E105K/0.85, "CAP, CERM, 1 µF, 25 V, +/- 10%, X7R, 1206"
C13: "CAP, CERM, 1000pF, 400V, +/-20%, Y5U, Disc, 9.3x12.5mm"
C14 C15: "CAP, CERM, 0.1uF, 50V, +/-10%, X7R, 0805"
C16 C17 C18 C19 C20 C22 C23: "CAP, CERM, 1uF, 25V, +/-10%, X7R, 0805"
C21 C24: "CAP, AL, 22uF, 35V, +/-20%, TH"
D1: "Diode, Ultrafast, 100V, 0.15A, SOD-123"
D2 D9 D10 D11: "Diode, Ultrafast, 600 V, 3 A, SMC"
D3 D5 D7 D8 D12 D13: library part bat54-7-F, "Diode, Schottky, 30V, 0.2A, SOT-23"
D4 D6: "Diode, Superfast Rectifier, 100V, 3A, SMB"
D14 D15: "Diode, Zener, 5.6V, 500mW, SOD-123"
FC1 FC2: "Fuse Holder, 10A, TH"
FID1 FID2 FID3: "Fiducial mark.  There is nothing to buy or mount."
H1 H2 H3 H4: "Standoff, Hex, 0.5\"L #6-32 Nylon"
H5 H6 H7 H8: "HEX STANDOFF 6-32 NYLON 1-3/4\""
H27 H28 H29 H30 H31 H32: "MACHINE SCREW PAN PHILLIPS M3 5mm"
HS1 HS2 HS3: "HEATSINK VERT MAX CLIP, BLACK, 2 INCHES"
J1 J2: library part ED120/2DS, "TERMINAL BLOCK 5.08MM VERT 2POS, TH"
J3 J4: "Terminal 70A Lug"
J5: "Receptacle, 7x2, 2mm, TH"
L1: "Inductor, Shielded, ?, 2uH, A, 0.0009 ohm, TH"
L2: "Inductor, Shielded, ?, 26uH, A, 0.027 ohm, TH"
Logo1: library part TI_Logo, "Texas Instrument Corporate Signature"
LOGO2 LOGO5 LOGO8: library part IEC_HighVoltage, "IEC 61010-1 High Voltage Warning"
LOGO3 LOGO4 LOGO6 LOGO7: library part IEC_HotSurface, "IEC 61010-1 Hot Surface Warning"
Logo9: library part Pb-Free
Q1 Q2 Q3 Q4: "MOSFET, N-CH, 650V, 20.7A, TO-220AB"
Q5 Q8: library part "MMBT2222A, Fairchild Semiconductor", "Transistor, NPN, 40V, 0.15A, SOT-23"
Q6 Q7: "MOSFET, N-CH, 80V, 100A, TO-220AB"
R1: "RES, 48.7 ohm, 1%, 0.125W, 0805"
R2: "RES, 4.87k ohm, 1%, 0.125W, 0805"
R3 R12 R14: "RES, 1.0Meg ohm, 5%, 0.25W, 1206"
R4 R5 R13 R15: "RES, 3.01 ohm, 1%, 0.125W, 0805"
R6: "RES, 100 k, 1%, 1 W, 2512"
R7 R8: "RES, 1.00k ohm, 1%, 2W, 4527"
R9: "RES, 49.9, 1%, 0.125 W, 0805"
R10 R11 R16 R17 R24 R25: "RES, 10.0k ohm, 1%, 0.125W, 0805"
R18 R19: "RES, 2.20 ohm, 1%, 0.125W, 0805"
R20 R26 R27 R30 R32 R34: "RES, 7.15k ohm, 1%, 0.125W, 0805"
R21 R22: "RES, 6.19 ohm, 1%, 0.125W, 0805"
R23 R29: "RES, 5.11 ohm, 1%, 0.125W, 0805"
R28 R31 R33 R35: "RES, 5.11k ohm, 1%, 0.125W, 0805"
T1: "Transformer, 20 mH, TH"
T2: "Transformer, 2.75mH, TH"
TP1 TP4 TP8 TP10: library part 5000, "Test Point, Miniature, Red, TH"
TP2 TP3 TP7: library part 5002, "Test Point, Miniature, White, TH"
TP5 TP6 TP9 TP11: library part 5001, "Test Point, Miniature, Black, TH"
U1 U2: "High-Speed,4A, 600V High-side Low-side Gate Driver Device, D0014A"
U3: "Dual 5-A High-Speed Low-Side Gate Driver, D0008A"
U4: "150 Mbps Quad Channels, 4 / 0, Digital Isolator, 3.3 V / 5 V, -40 to +125 degC, 16-pin SOIC (DW), Green (RoHS & no Sb/Br)"
ZZ1 ZZ2 ZZ3 ZZ4: library part AssemblyNote

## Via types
v1: diameter 32, hole 16, Top Layer to Bottom Layer, 116 vias
v2: diameter 50, hole 28, Top Layer to Bottom Layer, tented both sides, 52 vias

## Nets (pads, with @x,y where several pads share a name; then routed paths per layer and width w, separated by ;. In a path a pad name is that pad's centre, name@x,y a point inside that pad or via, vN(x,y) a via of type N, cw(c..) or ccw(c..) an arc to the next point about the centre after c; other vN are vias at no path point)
CS: D1.1 J5.2 R1.1 | length 3309.7
  Top Layer w31.5: v2(745,255.91) 745,225 907.01,62.99 2933.28,62.99 2950.59,45.68 2994.29,45.68 3011.6,62.99 3375.71,62.99 3444.88,132.17 3444.88,286.44 3487.14,328.7 J5.2@3527.8,328.7
  Bottom Layer w30: D1.1@670,395 670,390 745,390 v2(745,255.91)
GND: C1.1 C4.2 C5.2 C6.2 C7.2 C8.2 C9.1 C10.1 C11.1 C12.1 C13.1 C18.1 C22.1 C23.1 C24.2 D12.1 D13.1 D15.2 HS3.1 HS3.2 J4.1 J5.7 J5.11 J5.12 Q6.3 Q7.3 R1.2 R2.2 R6.2 R24.2 R25.2 R28.1 R31.1 R33.1 R35.1 T1.3 TP5.1 TP11.1 U3.3 U4.2 U4.8 | length 8599.4
  Top Layer w23.62: v2@2720.47,267.72 v2(2732.28,279.53) 2787.4,334.65 v2(2972.48,334.65) 2972.48,452.71 v2(2972.44,452.76) ; 2832.68,155.51 2846.46,141.73 ; v2(2972.44,98.43) 2972.44,141.73 v2(2972.44,216.54)
  Top Layer w30: v2(2279.92,141.73) 2405.91,267.72 2720.47,267.72 2832.68,155.51 ; 2846.46,141.73 2890.16,141.73 ; J5.12@3921.3,328.7 3921.3,385.47 4140.83,605 v2(4765,605) 4807.76,605 v2(4931.1,728.35)
  Top Layer w31.5: v2(1571.26,122.05) 1869.29,122.05 v2(1983.46,236.22) ; v2@2004.33,230.32 2092.91,141.73 v2(2279.92,141.73) ; 2890.16,141.73 2972.44,141.73 ; v2(2972.44,216.54) 3222.09,216.54 3462.24,456.69 3793.31,456.69 3921.3,328.7 3921.3,250 3866.05,194.75 3819.72,194.75 3764.47,250 J5.7@3763.9,250
  Top Layer w50: TP11.1@5100,100 5100,165 5262.2,327.2 C24.2@5262.2,445.59
  Bottom Layer w23.62: v2@2972.44,106.3 2980.31,98.43 R31.1@3045.55,98.43 ; v2(2972.44,216.54) R28.1@3045.55,216.54 ; v2(2972.44,452.76) R33.1@3045.55,452.76 ; v2(2972.48,334.65) R35.1@3045.55,334.65
  Bottom Layer w30: R2.2@635,490 635,485 835,485 ; 835,225 835,485 ; T1.3@950,625 835,510 835,485 ; v2@2274.29,156.93 2274.29,210.63 2276.97,213.31 U4.2@2276.97,316.93 ; D12.1@4620.08,498.03 D12.1@4628.03,498.03 ; D12.1@4622.5,492.5 D12.1@4628.03,498.03 ; v2(4765,605) 4701.85,605 4661.42,564.57 4661.42,507.87 4651.57,498.03 D12.1@4628.03,498.03 ; C18.1@4865,805 4931.1,738.9 v2(4931.1,728.35) ; v2@4920.51,515 v2(4921.26,515.75) 5033.96,515.75 ; D13.1@5037.4,576.77 5037.4,519.19 5033.96,515.75 ; C24.2@5262.2,445.59 5158.31,445.59 5153.94,441.22 5090.67,441.22 5033.96,497.93 5033.96,515.75 ; R25.2@5825,870 5825,875 5830,880 Q6.3@5830,960
  Bottom Layer w31.5: 835,225 937.95,122.05 v2(1571.26,122.05) ; U4.8@1976.97,316.93 1976.97,242.72 v2(1983.46,236.22) ; v2@2738.09,275.1 D15.2@2791.73,275.1 ; J5.11@3920.73,250 3921.3,250 J5.12@3921.3,328.7 ; U3.3@4765,515 v2(4765,605)
  Bottom Layer w50: C6.2@6824,1850 6825,1850 6825,1750 C9.1@6830,1750 ; C5.2@6824,2300 6825,2300 6825,2200 C12.1@6830,2200 ; C4.2@6824,2750 6825,2750 C11.1@6830,2650 ; C10.1@6830,1300 6825,1305 C7.2@6825,1375 ; C7.2@6825,1375 6824,1376 6824,1400 6825,1400 C7.2@6825,1375
  other v1: 6332.91,3255.32 6372.91,3255.32 6412.91,3255.32 6899.17,3255.32 6939.17,3255.32 6979.17,3255.32 7019.17,3255.32 6332.91,3295.32 6899.17,3295.32 6939.17,3295.32 6979.17,3295.32 7019.17,3295.32 6332.91,3335.32 6899.17,3335.32 6939.17,3335.32 6979.17,3335.32 7019.17,3335.32 6899.17,3375.32 6939.17,3375.32 6979.17,3375.32 7019.17,3375.32 6899.17,3415.32 6939.17,3415.32 6979.17,3415.32 7019.17,3415.32 6899.17,3455.32 6939.17,3455.32 6979.17,3455.32 7019.17,3455.32 6899.17,3505.32 6939.17,3505.32 6979.17,3505.32 7019.17,3505.32 6899.17,3545.32 6939.17,3545.32 6979.17,3545.32 7019.17,3545.32 6899.17,3585.32 6939.17,3585.32 6979.17,3585.32 7019.17,3585.32 6332.91,3625.32 6899.17,3625.32 6939.17,3625.32 6979.17,3625.32 7019.17,3625.32 6332.91,3665.32 6899.17,3665.32 6939.17,3665.32 6979.17,3665.32 7019.17,3665.32 6332.91,3705.32 6372.91,3705.32 6412.91,3705.32 6899.17,3705.32 6939.17,3705.32 6979.17,3705.32 7019.17,3705.32
NetC1_2: C1.2 D4.1 D6.1 R6.1 R7.2 R8.2
NetC2_2: C2.2 C3.1 FC2.1 FC2.2 R3.2 T1.2 TP1.1 | length 870.4
  Top Layer w30: TP1.1@150,1325 T1.2@450,1325
  Bottom Layer w50: 125,2775 150,2750 R3.2@685.04,2750
NetC4_1: C4.1 C5.1 C6.1 C7.1 C8.1 C9.2 C10.2 C11.2 C12.2 J3.1 L1.14 R7.1 R8.1 R9.2 TP3.1 TP4.1 | length 898.2
  Bottom Layer w30: R9.2@5845,100 TP3.1@6000,100 6225,325 J3.1@6650,325
  other v1: 6332.91,100 6372.91,100 6412.91,100 6899.17,100 6939.17,100 6979.17,100 7019.17,100 6332.91,140 6899.17,140 6939.17,140 6979.17,140 7019.17,140 6332.91,180 6899.17,180 6939.17,180 6979.17,180 7019.17,180 6899.17,220 6939.17,220 6979.17,220 7019.17,220 6899.17,260 6939.17,260 6979.17,260 7019.17,260 6899.17,300 6939.17,300 6979.17,300 7019.17,300 6899.17,350 6939.17,350 6979.17,350 7019.17,350 6899.17,390 6939.17,390 6979.17,390 7019.17,390 6899.17,430 6939.17,430 6979.17,430 7019.17,430 6332.91,470 6899.17,470 6939.17,470 6979.17,470 7019.17,470 6332.91,510 6899.17,510 6939.17,510 6979.17,510 7019.17,510 6332.91,550 6372.91,550 6412.91,550 6899.17,550 6939.17,550 6979.17,550 7019.17,550
NetC14_1: C14.1 D3.1 L2.1 L2.2 L2.3 L2.4 Q1.3 Q3.2 R11.2 U1.11 | length 1982.9
  Bottom Layer w30: 1708.66,2090.55 1708.66,2192.91 1960,2444.25 1960,2471.81 1974.13,2485.94 1974.13,2490.16 1976.2,2492.22 2167.22,2492.22 2225,2550 2225,2725 Q3.2@2200,2725 ; U1.11@1738.58,1210.63 C14.1@1738.58,1308.78
  Bottom Layer w31.5: D3.1@1608.27,1395.67 1624.02,1395.67 1690.94,1328.74 1718.62,1328.74 ; D3.1@1608.27,1395.77 1590.55,1395.77 1590.55,1972.44 1708.66,2090.55
NetC14_2: C14.2 D10.1 U1.13 | length 916.8
  Top Layer w31.5: v2@1433.46,1185.04 v2(1440.94,1192.52) 1492.52,1244.09 1827.17,1244.09 v2(1896.06,1312.99)
  Bottom Layer w30: D10.1@1240.16,1114.25 1318.43,1192.52 v2(1440.94,1192.52)
  Bottom Layer w31.5: U1.13@1838.58,1210.63 1838.58,1307.2 1832.8,1312.99 v2(1896.06,1312.99)
NetC15_1: C15.1 D5.1 Q2.3 Q4.2 R10.1 T2.3 U2.11 | length 1092.1
  Bottom Layer w30: C15.1@2377.72,1312.99 2374.02,1316.69 2374.02,1381.89 2405.51,1413.39 ; D5.1@2474.41,1411.42 2407.48,1411.42 2405.51,1413.39 ; Q2.3@2775,2025 2775,1910 2615,1750 2615,1675 2500,1560 2434.02,1560 2405.51,1531.5 2405.51,1413.39
  Bottom Layer w31.5: U2.11@2368.5,1210.63 2368.5,1308.78 C15.1@2372.72,1312.99
NetC15_2: C15.2 D11.1 U2.13 | length 472.3
  Top Layer w31.5: v2(2545.67,1322.83) 2614.57,1322.83 2663.78,1273.62 v2@2663.78,1263.78
  Bottom Layer w31.5: U2.13@2468.5,1210.63 2468.5,1308.94 2472.56,1312.99 2482.4,1322.83 v2(2545.67,1322.83) ; D11.1@2661.73,1125.98 2673.62,1137.87 v2(2673.62,1263.78)
NetC19_2: C19.2 Q5.2 U4.10 U4.16 | length 739.2
  Top Layer w31.5: v2(2085.86,843.81) 2167.85,761.81 v2(2329.13,761.81)
  Bottom Layer w31.5: U4.10@2026.97,675.2 2026.97,784.92 v2(2085.86,843.81) ; U4.16@2329.13,678.27 v2(2329.13,761.81) ; 2342.05,691.18 2425.2,691.18 C19.2@2427.56,693.54 ; C19.2@2427.56,698.54 2432.56,693.54 2478.98,693.54 2500,714.57 Q5.2@2515.75,714.57
NetC21_1: C21.1 R23.2 TP8.1 | length 298.9
  Bottom Layer w31.5: TP8.1@1307.09,704.72 1389.76,787.4 1559.72,787.4 R23.2@1568.2,778.93
NetC22_2: C22.2 Q8.2 U4.1 | length 259.2
  Bottom Layer w31.5: U4.1@2326.97,316.93 2326.97,263.31 2359.29,230.99 C22.2@2359.29,215.63 ; C22.2@2359.29,210.63 C22.2@2359.29,215.63 ; Q8.2@2468.8,143.13 2431.79,143.13 C22.2@2359.29,215.63
NetC24_1: C24.1 R29.2 TP10.1 | length 648.3
  Top Layer w50: C24.1@5262.2,525.59 5331.1,525.59 5370.47,486.22 5370.47,275.47 5300,205 TP10.1@5300,100
  Bottom Layer w31.5: R29.2@5238.31,624.02 5262.2,600.12 C24.1@5262.2,525.59
NetD1_2: D1.2 R2.1 T1.5 | length 447.3
  Bottom Layer w30: T1.5@450,625 450,585 540,495 D1.2@540,395 ; D1.2@540,395 540,485 D1.2@540,395
NetD2_1: D2.1 Q1.2 Q2.2 T1.1
NetD2_2: D2.2 D9.1 L2.5 L2.6 L2.7 L2.8 T2.1
NetD3_3: D3.3 R4.1 U1.12 | length 1650.7
  Bottom Layer w30: D3.3@1533.46,1358.27 1531.5,1356.3 1531.5,1181.33 1572.51,1140.32 1754.66,1140.32 1788.58,1174.25 U1.12@1788.58,1210.63 ; 1655,2220.47 1791.34,2356.81 R4.1@1791.34,2399.88
  Bottom Layer w31.5: D3.3@1533.46,1358.27 1533.46,1994.09 1655,2115.63 1655,2220.47
NetD4_2: D4.2 Q7.2 T2.10
NetD5_3: D5.3 R5.1 U2.12 | length 745.9
  Bottom Layer w30: D5.3@2549.21,1448.82 2549.21,1415.75 2618.11,1346.85 2618.11,1274.61 2597.48,1253.98 ; D5.3@2550,1449.61 2550,1475.2 2574.8,1500 R5.1@2720,1500
  Bottom Layer w31.5: U2.12@2418.5,1210.63 2418.5,1173.19 2452.12,1139.57 2534.89,1139.57 2558.06,1162.75 2558.06,1214.57 2597.48,1253.98
NetD6_2: D6.2 Q6.2 T2.9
